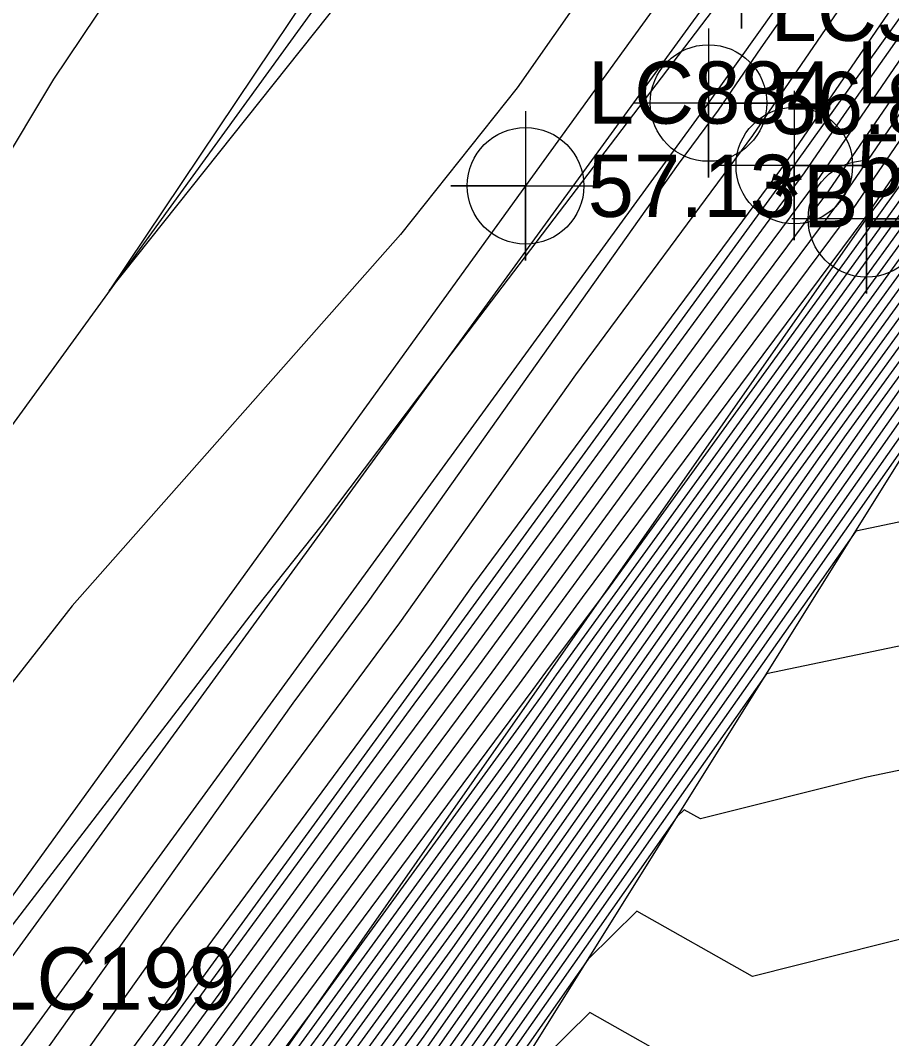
# Model space of a CAD drawing. Extents: x 2188792 to 2191981, y 386090 to 389710.
# Drawn here: x 2190030.64 to 2190065.66, y 387443.12 to 387484.06 of the extents above; entities that cross this region are included whole.
import ezdxf

# ---------------------------------------------------------------- set-up
doc = ezdxf.new("R2010")
doc.units = 0
for name, color, linetype in [('DTM Contours Major', 7, 'Continuous'), ('DTM Contours Minor', 7, 'Continuous'), ('Exist DTM Breakline', 7, 'Continuous'), ('Exist DTM Breakline Cogo Comment', 7, 'Continuous'), ('Exist DTM Breakline Cogo Elevation', 7, 'Continuous'), ('Exist DTM Breakline Cogo Number', 7, 'Continuous'), ('Exist DTM Breakline Cogo Point CELL', 7, 'Continuous'), ('Exist Roads EOP', 7, 'Continuous'), ('Exist Roads EOP Cogo Number', 7, 'Continuous'), ('Exist Roads EOP Cogo Point CELL', 7, 'Continuous'), ('Exist Roads EOT', 7, 'Continuous'), ('Exist Roads EOT Cogo Elevation', 7, 'Continuous'), ('Exist Roads EOT Cogo Number', 7, 'Continuous'), ('Exist Roads EOT Cogo Point CELL', 7, 'Continuous')]:
    doc.layers.add(name, color=color, linetype=linetype)

msp = doc.modelspace()

# ---------------------------------------------------------------- linework, layer by layer
at = {"layer": 'DTM Contours Major'}
for points in [[(2189985.275, 387383.669), (2189994.24, 387397.334), (2190000.542, 387406.584), (2190005.068, 387412.932), (2190013.175, 387425.126), (2190018.833, 387434.036), (2190019.851, 387435.22), (2190023.561, 387439.509), (2190030.225, 387447.562), (2190040.144, 387460.464), (2190042.779, 387463.794), (2190047.272, 387469.736), (2190059.404, 387485.693), (2190062.073, 387489.527), (2190073.957, 387506.082), (2190075.657, 387508.517), (2190091.037, 387529.933), (2190091.267, 387530.33), (2190091.329, 387530.517), (2190091.393, 387530.607), (2190108.388, 387554.062)], [(2190106.731, 387542.448), (2190099.469, 387532.426), (2190096.508, 387528.215), (2190094.775, 387523.014), (2190093.569, 387521.301), (2190083.683, 387507.247), (2190079.859, 387502.134), (2190066.248, 387482.85), (2190062.633, 387477.566), (2190059.105, 387472.827), (2190048.491, 387458.326), (2190044.873, 387453.452), (2190030.711, 387434.1), (2190030.018, 387433.137), (2190027.341, 387429.417), (2190023.779, 387424.466), (2190009.82, 387405.068), (2190006.105, 387399.906), (2189992.299, 387380.721)], [(2190110.745, 387540.41), (2190105.891, 387533.526), (2190105.582, 387533.077), (2190100.754, 387526.228), (2190099.627, 387524.62), (2190095.823, 387519.225), (2190089.739, 387510.691), (2190082.098, 387500.475), (2190078.739, 387495.716), (2190071.019, 387484.433), (2190064.89, 387475.89), (2190054.344, 387461.328), (2190051.756, 387457.851), (2190051.243, 387457.151), (2190036.94, 387437.88), (2190033.304, 387432.912), (2190030.391, 387428.863), (2190029.739, 387427.956), (2190014.659, 387406.997), (2190012.23, 387403.623), (2189995.968, 387381.02)], [(2190114.284, 387538.324), (2190111.626, 387535.207), (2190109.01, 387531.496), (2190106.262, 387527.516), (2190103.844, 387524.086), (2190101.173, 387520.274), (2190099.676, 387517.333), (2190092.293, 387506.847), (2190085.473, 387497.899), (2190075.878, 387485.31), (2190067.614, 387473.791), (2190061.717, 387465.648), (2190054.342, 387455.145), (2190047.627, 387445.581), (2190036.85, 387430.761), (2190035.701, 387429.225), (2190033.337, 387425.963), (2190026.852, 387417.298), (2190015.609, 387401.795), (2190008.751, 387392.635)], [(2190111.185, 387537.809), (2190107.45, 387532.511), (2190105.922, 387530.297), (2190102.299, 387525.157), (2190098.297, 387519.445), (2190097.984, 387518.83), (2190086.635, 387502.712), (2190083.893, 387499.114), (2190080.036, 387494.053), (2190066.252, 387474.84), (2190056.415, 387461.258), (2190052.824, 387456.143), (2190049.554, 387451.486), (2190035.249, 387431.813), (2190034.794, 387431.205), (2190031.653, 387426.871), (2190029.033, 387423.37), (2190014.005, 387402.646), (2190010.979, 387398.605), (2189996.34, 387378.433)], [(2190115.906, 387537.107), (2190112.067, 387532.606), (2190110.569, 387530.481), (2190106.602, 387524.736), (2190105.389, 387523.015), (2190104.049, 387521.102), (2190101.368, 387515.835), (2190097.95, 387510.981), (2190087.053, 387496.683), (2190071.72, 387476.566), (2190068.976, 387472.742), (2190067.018, 387470.039), (2190055.86, 387454.147), (2190045.7, 387439.676), (2190038.452, 387429.71), (2190036.608, 387427.245), (2190035.022, 387425.056), (2190024.671, 387411.226), (2190017.214, 387400.943), (2190006.522, 387386.664)], [(2190117.527, 387535.891), (2190112.507, 387530.004), (2190112.128, 387529.466), (2190106.942, 387521.955), (2190106.934, 387521.944), (2190106.925, 387521.931), (2190106.753, 387521.593), (2190104.953, 387515.237), (2190106.299, 387512.1), (2190099.551, 387498.387), (2190090.794, 387477.182), (2190084.115, 387462.685), (2190060.634, 387457.786), (2190057.378, 387453.148), (2190043.772, 387433.771), (2190040.054, 387428.658), (2190037.515, 387425.265), (2190036.706, 387424.148), (2190022.49, 387405.154), (2190018.819, 387400.092), (2190004.294, 387380.694)]]:
    msp.add_lwpolyline(points, dxfattribs=at)
at = {"layer": 'DTM Contours Minor'}
for points in [[(2189955.308, 387371.872), (2189966.747, 387385.386), (2189969.936, 387388.826), (2189985.972, 387407.987), (2189987.388, 387410.082), (2189997.235, 387426.377), (2190000.201, 387430.738), (2190011.219, 387448.654), (2190017.983, 387459.688), (2190025.097, 387470.227), (2190031.989, 387481.689), (2190038.237, 387491.023), (2190049.61, 387508.8), (2190053.061, 387513.633), (2190063.181, 387529.704), (2190065.491, 387532.944), (2190080.791, 387553.075)], [(2189991.5, 387387.944), (2190006.309, 387407.959), (2190009.862, 387412.875), (2190024.083, 387432.111), (2190024.846, 387433.166), (2190027.155, 387436.291), (2190041.613, 387456.61), (2190044.615, 387460.675), (2190057.101, 387478.28), (2190058.7, 387480.441), (2190060.418, 387482.951), (2190075.921, 387505.01), (2190076.691, 387506.131), (2190089.632, 387524.531), (2190091.732, 387528.156), (2190092.365, 387530.057), (2190093.008, 387530.971), (2190108.057, 387551.739)], [(2189998.486, 387394.909), (2190007.419, 387406.982), (2190016.684, 387419.801), (2190025.109, 387431.197), (2190026.917, 387433.7), (2190028.281, 387435.545), (2190036.815, 387447.54), (2190045.891, 387459.829), (2190052.965, 387469.804), (2190060.087, 387479.431), (2190067.74, 387490.608), (2190077.205, 387504.075), (2190082.418, 387511.662), (2190090.831, 387523.625), (2190092.196, 387525.982), (2190093.401, 387529.596), (2190094.623, 387531.335), (2190107.725, 387549.417)], [(2189990.911, 387381.736), (2190005.473, 387401.874), (2190008.529, 387406.005), (2190023.505, 387426.727), (2190026.134, 387430.283), (2190028.989, 387434.234), (2190029.406, 387434.799), (2190032.018, 387438.47), (2190047.166, 387458.984), (2190048.83, 387461.329), (2190061.474, 387478.421), (2190075.063, 387498.265), (2190078.489, 387503.14), (2190088.144, 387517.193), (2190092.031, 387522.719), (2190092.661, 387523.808), (2190094.437, 387529.136), (2190096.239, 387531.699), (2190107.394, 387547.094)], [(2190107.063, 387544.771), (2190097.854, 387532.062), (2190095.472, 387528.675), (2190093.273, 387522.075), (2190093.123, 387521.862), (2190080.566, 387504.01), (2190079.411, 387502.466), (2190063.75, 387480.277), (2190062.143, 387477.929), (2190060.575, 387475.822), (2190047.94, 387458.561), (2190046.46, 387456.566), (2190030.192, 387434.337), (2190029.944, 387433.992), (2190026.861, 387429.709), (2190025.602, 387427.959), (2190009.337, 387405.358), (2190008.133, 387403.683), (2189991.814, 387381.006)], [(2190110.657, 387540.931), (2190105.579, 387533.729), (2190105.514, 387533.633), (2190100.445, 387526.443), (2190100.195, 387526.086), (2190095.357, 387519.224), (2190093.956, 387517.258), (2190081.65, 387500.807), (2190076.24, 387493.143), (2190064.592, 387476.117), (2190053.226, 387460.846), (2190050.693, 387457.386), (2190038.527, 387440.994), (2190032.785, 387433.149), (2190030.317, 387429.718), (2190029.259, 387428.248), (2190016.483, 387410.491), (2190011.748, 387403.912), (2189997.995, 387384.797)], [(2190106.4, 387540.126), (2190101.085, 387532.79), (2190097.544, 387527.754), (2190096.277, 387523.953), (2190094.014, 387520.74), (2190086.8, 387510.483), (2190080.306, 387501.803), (2190068.746, 387485.423), (2190063.122, 387477.204), (2190057.635, 387469.832), (2190049.041, 387458.091), (2190043.287, 387450.338), (2190031.229, 387433.862), (2190030.093, 387432.282), (2190027.82, 387429.125), (2190021.955, 387420.972), (2190010.302, 387404.779), (2190004.078, 387396.129), (2189992.784, 387380.435)], [(2190110.833, 387539.89), (2190106.203, 387533.323), (2190105.65, 387532.521), (2190101.063, 387526.014), (2190099.059, 387523.154), (2190096.289, 387519.225), (2190085.523, 387504.124), (2190082.546, 387500.144), (2190081.237, 387498.289), (2190078.229, 387493.893), (2190065.162, 387475.68), (2190052.174, 387457.746), (2190051.61, 387456.942), (2190051.096, 387456.21), (2190042.68, 387444.636), (2190035.353, 387434.765), (2190033.823, 387432.674), (2190030.466, 387428.008), (2190030.218, 387427.664), (2190012.835, 387403.503), (2190012.712, 387403.333), (2190011.047, 387401.019), (2189995.118, 387379.07)], [(2190110.921, 387539.37), (2190106.515, 387533.12), (2190105.718, 387531.965), (2190101.372, 387525.8), (2190098.49, 387521.687), (2190096.755, 387519.226), (2190085.439, 387503.353), (2190083.241, 387500.231), (2190082.946, 387499.844), (2190082.531, 387499.299), (2190065.435, 387475.47), (2190053.235, 387458.624), (2190051.913, 387456.742), (2190050.71, 387455.029), (2190034.287, 387432.444), (2190034.25, 387432.393), (2190030.642, 387427.415), (2190030.342, 387427.014), (2190013.042, 387403.157), (2190012.316, 387402.187), (2189995.424, 387378.911)], [(2190090.433, 387538.558), (2190081.858, 387525.513), (2190076.832, 387518.603), (2190064.309, 387500.724), (2190060.643, 387495.686), (2190050.609, 387481.34), (2190045.922, 387475.444), (2190032.722, 387460.512), (2190025.807, 387451.7), (2190018.593, 387443.361), (2190005.665, 387428.328), (2190000.783, 387420.64), (2189989.434, 387408.614), (2189987.654, 387405.624), (2189978.015, 387387.397), (2189970.823, 387375.147), (2189965.311, 387365.046), (2189957.256, 387351.588)], [(2190111.009, 387538.849), (2190106.827, 387532.917), (2190105.786, 387531.409), (2190101.681, 387525.586), (2190097.922, 387520.221), (2190097.221, 387519.226), (2190092.649, 387512.813), (2190084.372, 387501.058), (2190083.262, 387499.601), (2190081.699, 387497.551), (2190065.707, 387475.26), (2190054.295, 387459.502), (2190052.217, 387456.543), (2190050.325, 387453.848), (2190034.608, 387432.234), (2190034.431, 387431.997), (2190030.979, 387427.234), (2190029.906, 387425.799), (2190013.363, 387402.987), (2190011.87, 387400.993), (2189995.729, 387378.751)], [(2190111.097, 387538.329), (2190107.139, 387532.714), (2190105.854, 387530.853), (2190101.99, 387525.371), (2190097.722, 387519.28), (2190097.646, 387519.13), (2190085.504, 387501.885), (2190083.578, 387499.358), (2190080.867, 387495.802), (2190065.979, 387475.05), (2190055.355, 387460.38), (2190052.52, 387456.343), (2190049.939, 387452.667), (2190034.928, 387432.023), (2190034.612, 387431.601), (2190031.316, 387427.052), (2190029.469, 387424.585), (2190013.684, 387402.816), (2190011.424, 387399.799), (2189996.034, 387378.592)], [(2190114.608, 387538.081), (2190111.714, 387534.687), (2190109.321, 387531.293), (2190106.33, 387526.96), (2190104.153, 387523.872), (2190101.748, 387520.44), (2190100.015, 387517.033), (2190093.424, 387507.674), (2190085.789, 387497.656), (2190075.046, 387483.561), (2190067.886, 387473.581), (2190062.777, 387466.526), (2190054.645, 387454.945), (2190047.241, 387444.4), (2190037.171, 387430.551), (2190035.882, 387428.829), (2190033.674, 387425.782), (2190026.416, 387416.084), (2190015.93, 387401.624), (2190008.305, 387391.441)], [(2190106.069, 387537.803), (2190102.7, 387533.154), (2190098.58, 387527.294), (2190097.779, 387524.892), (2190094.46, 387520.178), (2190089.917, 387513.72), (2190080.754, 387501.471), (2190071.244, 387487.996), (2190063.612, 387476.842), (2190056.166, 387466.837), (2190049.592, 387457.856), (2190041.7, 387447.223), (2190031.748, 387433.624), (2190030.167, 387431.428), (2190028.3, 387428.833), (2190020.131, 387417.478), (2190010.784, 387404.49), (2190002.05, 387392.352)], [(2190114.933, 387537.837), (2190111.802, 387534.167), (2190109.633, 387531.09), (2190106.398, 387526.404), (2190104.462, 387523.658), (2190102.324, 387520.605), (2190100.353, 387516.734), (2190094.556, 387508.5), (2190086.105, 387497.413), (2190074.214, 387481.812), (2190068.159, 387473.371), (2190063.837, 387467.405), (2190054.949, 387454.746), (2190046.856, 387443.219), (2190037.491, 387430.341), (2190036.064, 387428.433), (2190034.011, 387425.6), (2190025.98, 387414.869), (2190016.251, 387401.454), (2190007.859, 387390.247)], [(2190111.274, 387537.288), (2190107.762, 387532.308), (2190105.99, 387529.741), (2190102.608, 387524.943), (2190098.873, 387519.611), (2190098.323, 387518.531), (2190087.767, 387503.539), (2190084.209, 387498.871), (2190079.204, 387492.304), (2190066.524, 387474.631), (2190057.476, 387462.136), (2190053.128, 387455.944), (2190049.168, 387450.305), (2190035.569, 387431.603), (2190034.975, 387430.809), (2190031.99, 387426.689), (2190028.597, 387422.156), (2190014.326, 387402.476), (2190010.533, 387397.411), (2189996.645, 387378.274)], [(2190115.581, 387537.351), (2190111.979, 387533.126), (2190110.257, 387530.684), (2190106.534, 387525.292), (2190105.08, 387523.229), (2190103.474, 387520.937), (2190101.03, 387516.135), (2190096.819, 387510.154), (2190086.737, 387496.926), (2190072.551, 387478.315), (2190068.704, 387472.952), (2190065.958, 387469.161), (2190055.556, 387454.346), (2190046.085, 387440.857), (2190038.132, 387429.92), (2190036.426, 387427.641), (2190034.685, 387425.237), (2190025.107, 387412.441), (2190016.893, 387401.114), (2190006.968, 387387.858)], [(2190115.257, 387537.594), (2190111.89, 387533.646), (2190109.945, 387530.887), (2190106.466, 387525.848), (2190104.771, 387523.443), (2190102.899, 387520.771), (2190100.691, 387516.434), (2190095.687, 387509.327), (2190086.421, 387497.169), (2190073.383, 387480.063), (2190068.431, 387473.162), (2190064.898, 387468.283), (2190055.253, 387454.546), (2190046.47, 387442.038), (2190037.812, 387430.13), (2190036.245, 387428.037), (2190034.348, 387425.419), (2190025.544, 387413.655), (2190016.572, 387401.284), (2190007.414, 387389.052)], [(2190078.772, 387537.414), (2190063.592, 387516.122), (2190062.167, 387513.859), (2190049.516, 387496.136), (2190048.045, 387493.838), (2190034.215, 387473.177), (2190049.645, 387492.586), (2190050.943, 387494.441), (2190063.751, 387512.041), (2190065.514, 387514.559), (2190081.303, 387536.264)], [(2190116.23, 387536.864), (2190112.155, 387532.085), (2190110.88, 387530.278), (2190106.67, 387524.18), (2190105.698, 387522.801), (2190104.624, 387521.268), (2190101.706, 387515.536), (2190099.082, 387511.808), (2190087.368, 387496.44), (2190070.888, 387474.817), (2190069.248, 387472.532), (2190068.078, 387470.917), (2190056.163, 387453.947), (2190045.314, 387438.495), (2190038.773, 387429.499), (2190036.789, 387426.849), (2190035.358, 387424.874), (2190024.235, 387410.012), (2190017.535, 387400.773), (2190006.077, 387385.47)], [(2190111.362, 387536.768), (2190108.074, 387532.105), (2190106.058, 387529.185), (2190102.917, 387524.729), (2190099.448, 387519.777), (2190098.661, 387518.231), (2190088.898, 387504.366), (2190084.525, 387498.628), (2190078.373, 387490.556), (2190066.797, 387474.421), (2190058.536, 387463.014), (2190053.431, 387455.744), (2190048.783, 387449.124), (2190035.889, 387431.392), (2190035.157, 387430.413), (2190032.327, 387426.508), (2190028.161, 387420.942), (2190014.647, 387402.305), (2190010.087, 387396.217), (2189996.95, 387378.115)], [(2190116.554, 387536.621), (2190112.243, 387531.565), (2190111.192, 387530.075), (2190106.738, 387523.624), (2190106.007, 387522.586), (2190105.2, 387521.434), (2190102.045, 387515.236), (2190100.213, 387512.635), (2190087.684, 387496.197), (2190070.056, 387473.069), (2190069.521, 387472.322), (2190069.139, 387471.795), (2190056.467, 387453.747), (2190044.929, 387437.314), (2190039.093, 387429.289), (2190036.971, 387426.453), (2190035.695, 387424.693), (2190023.799, 387408.797), (2190017.856, 387400.603), (2190005.631, 387384.276)], [(2190117.203, 387536.134), (2190112.419, 387530.525), (2190111.816, 387529.669), (2190106.874, 387522.511), (2190106.625, 387522.158), (2190106.35, 387521.765), (2190102.721, 387514.637), (2190102.476, 387514.289), (2190097.206, 387507.375), (2190091.943, 387496.681), (2190089.034, 387489.636), (2190078.365, 387466.477), (2190064.22, 387463.525), (2190057.074, 387453.348), (2190044.158, 387434.952), (2190039.734, 387428.868), (2190037.333, 387425.661), (2190036.369, 387424.33), (2190022.926, 387406.369), (2190018.498, 387400.262), (2190004.74, 387381.888)], [(2190116.879, 387536.377), (2190112.331, 387531.045), (2190111.504, 387529.872), (2190106.806, 387523.067), (2190106.316, 387522.372), (2190105.775, 387521.599), (2190102.383, 387514.937), (2190101.345, 387513.462), (2190088, 387495.954), (2190079.019, 387484.171), (2190072.614, 387470.268), (2190067.806, 387469.265), (2190056.77, 387453.548), (2190044.543, 387436.133), (2190039.413, 387429.079), (2190037.152, 387426.057), (2190036.032, 387424.511), (2190023.362, 387407.583), (2190018.177, 387400.433), (2190005.185, 387383.082)], [(2190111.45, 387536.248), (2190108.386, 387531.902), (2190106.126, 387528.628), (2190103.226, 387524.514), (2190100.023, 387519.943), (2190098.999, 387517.932), (2190090.03, 387505.193), (2190084.841, 387498.385), (2190077.541, 387488.807), (2190067.069, 387474.211), (2190059.596, 387463.892), (2190053.735, 387455.544), (2190048.398, 387447.943), (2190036.21, 387431.182), (2190035.338, 387430.017), (2190032.664, 387426.326), (2190027.725, 387419.727), (2190014.968, 387402.135), (2190009.642, 387395.023)], [(2190117.852, 387535.647), (2190112.595, 387529.484), (2190112.44, 387529.263), (2190110.263, 387526.111), (2190109.543, 387521.58), (2190108.03, 387516.24), (2190111.326, 387508.562), (2190107.159, 387500.094), (2190092.553, 387464.728), (2190089.865, 387458.894), (2190064.663, 387453.635), (2190057.974, 387451.949), (2190057.323, 387452.317), (2190057.048, 387452.046), (2190043.387, 387432.59), (2190040.375, 387428.448), (2190037.696, 387424.869), (2190037.043, 387423.967), (2190022.054, 387403.94), (2190019.14, 387399.922), (2190003.848, 387379.5)], [(2190111.538, 387535.728), (2190108.698, 387531.699), (2190106.194, 387528.072), (2190103.535, 387524.3), (2190100.598, 387520.108), (2190099.338, 387517.632), (2190091.161, 387506.02), (2190085.157, 387498.142), (2190076.709, 387487.058), (2190067.341, 387474.001), (2190060.657, 387464.77), (2190054.038, 387455.345), (2190048.012, 387446.762), (2190036.53, 387430.972), (2190035.519, 387429.621), (2190033, 387426.145), (2190027.288, 387418.513), (2190015.288, 387401.965), (2190009.196, 387393.829)], [(2190105.738, 387535.48), (2190104.315, 387533.517), (2190099.616, 387526.833), (2190099.282, 387525.831), (2190094.906, 387519.617), (2190093.034, 387516.956), (2190081.202, 387501.139), (2190073.742, 387490.57), (2190064.102, 387476.479), (2190054.696, 387463.842), (2190050.142, 387457.621), (2190040.113, 387444.109), (2190032.267, 387433.387), (2190030.242, 387430.573), (2190028.78, 387428.54), (2190018.307, 387413.985), (2190011.266, 387404.201), (2190000.023, 387388.574)], [(2190130.789, 387441.565), (2190112.274, 387444.264), (2190108.666, 387430.2), (2190092.935, 387453.897), (2190060.074, 387445.612), (2190055.424, 387448.243), (2190053.462, 387446.307), (2190043.002, 387431.409), (2190040.695, 387428.237), (2190037.878, 387424.473), (2190037.38, 387423.785), (2190021.618, 387402.725), (2190019.461, 387399.752), (2190003.403, 387378.306)], [(2190106.764, 387389.602), (2190117.791, 387408.328), (2190115.282, 387409.044), (2190090.477, 387446.411), (2190062.175, 387439.276), (2190053.526, 387444.168), (2190049.875, 387440.567), (2190042.616, 387430.229), (2190041.015, 387428.027), (2190038.059, 387424.077), (2190037.716, 387423.604), (2190021.181, 387401.511), (2190019.782, 387399.581), (2190002.957, 387377.112)]]:
    msp.add_lwpolyline(points, dxfattribs=at)
at = {"layer": 'Exist DTM Breakline'}
for points in [[(2189987.902, 387384.357), (2190026.315, 387436.848), (2190058.298, 387480.734), (2190089.535, 387524.604)], [(2189991.613, 387381.125), (2190029.902, 387434.47), (2190061.751, 387478.219), (2190093.06, 387521.942)], [(2189994.964, 387379.15), (2190034.2, 387432.501), (2190064.649, 387476.075), (2190097.537, 387519.226)], [(2190002.292, 387375.33), (2190041.742, 387427.55), (2190069.653, 387472.22), (2190102.826, 387514.545)]]:
    msp.add_lwpolyline(points, dxfattribs=at)
at = {"layer": 'Exist DTM Breakline Cogo Point CELL'}
for points in [[(2190058.298, 387483.734), (2190058.298, 387477.734), (2190058.298, 387480.734), (2190061.298, 387480.734), (2190055.298, 387480.734)], [(2190061.751, 387481.219), (2190061.751, 387475.219), (2190061.751, 387478.219), (2190064.751, 387478.219), (2190058.751, 387478.219)], [(2190064.649, 387479.075), (2190064.649, 387473.075), (2190064.649, 387476.075), (2190067.649, 387476.075), (2190061.649, 387476.075)]]:
    msp.add_lwpolyline(points, dxfattribs=at)
for centre in [(2190058.298, 387480.734), (2190061.751, 387478.219), (2190064.649, 387476.075)]:
    msp.add_circle(centre, 2.344, dxfattribs=at)
at = {"layer": 'Exist Roads EOP'}
msp.add_lwpolyline([(2190335.128, 387868.989), (2190306.373, 387829.271), (2190274.581, 387784.921), (2190245.133, 387744.071), (2190214.553, 387701.741), (2190184.89, 387660.475), (2190157.493, 387622.204), (2190126.048, 387578.501), (2190091.216, 387530.568), (2190059.634, 387486.726), (2190026.932, 387441.783), (2189997.689, 387401.032), (2189957.023, 387344.154), (2189927.908, 387303.922), (2189889.008, 387250.224), (2189856.606, 387205.5), (2189825.68, 387162.612), (2189795.668, 387120.822), (2189765.955, 387079.619), (2189734.998, 387036.704), (2189703.849, 386993.356), (2189673.984, 386951.979), (2189643.253, 386909.427)], dxfattribs=at)
at = {"layer": 'Exist Roads EOP Cogo Point CELL'}
msp.add_lwpolyline([(2190059.634, 387489.726), (2190059.634, 387483.726), (2190059.634, 387486.726), (2190062.634, 387486.726), (2190056.634, 387486.726)], dxfattribs=at)
at = {"layer": 'Exist Roads EOT'}
for points in [[(2190333.162, 387868.755), (2190301.785, 387825.12), (2190269.645, 387780.315), (2190237.827, 387736.49), (2190205.816, 387692.275), (2190173.845, 387647.822), (2190143.211, 387605.324), (2190112.772, 387563.076), (2190082.117, 387520.492), (2190050.947, 387477.405), (2190019.959, 387434.524), (2189989.253, 387391.986)], [(2190174.375, 387667.889), (2190147.471, 387630.495), (2190115.247, 387585.778), (2190081.202, 387538.232), (2190049.502, 387494.256), (2190017.538, 387450.182), (2189987.334, 387408.357), (2189946.666, 387352.019), (2189917.402, 387311.129), (2189878.955, 387257.772), (2189846.565, 387212.819), (2189815.837, 387170.306), (2189785.374, 387128.351), (2189755.717, 387086.921), (2189724.953, 387044.041), (2189693.727, 387000.805), (2189663.933, 386959.217), (2189633.425, 386917.196)]]:
    msp.add_lwpolyline(points, dxfattribs=at)
at = {"layer": 'Exist Roads EOT Cogo Point CELL'}
msp.add_lwpolyline([(2190050.947, 387480.405), (2190050.947, 387474.405), (2190050.947, 387477.405), (2190047.947, 387477.405), (2190053.947, 387477.405)], dxfattribs=at)
msp.add_circle((2190050.947, 387477.405), 2.344, dxfattribs=at)

# ---------------------------------------------------------------- texts
at = {"layer": 'Exist DTM Breakline Cogo Comment'}
msp.add_text('*BL4005', height=2.5, dxfattribs=at).set_placement((2190060.798, 387475.734))
at = {"layer": 'Exist DTM Breakline Cogo Elevation'}
for s, p in [('56.86', (2190060.798, 387479.484)), ('56.36', (2190064.251, 387476.969))]:
    msp.add_text(s, height=2.5, dxfattribs=at).set_placement(p)
at = {"layer": 'Exist DTM Breakline Cogo Number'}
for s, p in [('LC35', (2190060.798, 387483.234)), ('LC36', (2190064.251, 387480.719))]:
    msp.add_text(s, height=2.5, dxfattribs=at).set_placement(p)
at = {"layer": 'Exist Roads EOP Cogo Number'}
msp.add_text('LC199', height=2.5, dxfattribs=at).set_placement((2190029.432, 387444.283))
at = {"layer": 'Exist Roads EOT Cogo Elevation'}
msp.add_text('57.13', height=2.5, dxfattribs=at).set_placement((2190053.447, 387476.155))
at = {"layer": 'Exist Roads EOT Cogo Number'}
msp.add_text('LC884', height=2.5, dxfattribs=at).set_placement((2190053.447, 387479.905))

doc.saveas('drawing.dxf')
